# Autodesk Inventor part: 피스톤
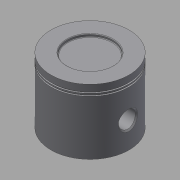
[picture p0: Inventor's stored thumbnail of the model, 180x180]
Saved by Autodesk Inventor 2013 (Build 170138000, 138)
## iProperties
Created: 2016-11
Part Number: 피스톤
Material: 강철, 탄소
Document SubType Name: Modeling
Designer: mduedu
Density: 1 g/cm^3
Author: mduedu
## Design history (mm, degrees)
sketch "스케치1"
  geometry: C1 r 30 at (0, 0); 1 further point
  constraints: 1 centre point, 1 coincident
  dimensions: "d0" = 60 diameter of C1
extrude "돌출1" new body sketch "스케치1" distance "d1" = 50; taper "d2" = 0 deg
sketch "스케치2"
  geometry: C1 r 28 at (0, 0); 1 further point
  constraints: 1 centre point, 1 coincident
  dimensions: "d3" = 56 diameter of C1
extrude "돌출2" cut sketch "스케치2" distance "d4" = 45; taper "d5" = 0 deg
sketch "스케치3"
  geometry: L1 (30, 0)-(30, 50) reference; L2 (30, 45)-(29, 45); L3 (29, 45)-(29, 44); L4 (29, 44)-(30, 44); L5 (30, 44)-(30, 45); L6 (30, 43)-(29, 43); L7 (29, 43)-(29, 42); L8 (29, 42)-(30, 42); L9 (30, 42)-(30, 43); L10 (30, 50)-(-30, 50) reference; L11 (0, 50)-(0, 0)
  constraints: 18 end point, 4 parallel, 3 equal length, 3 perpendicular, 2 horizontal, 2 point on line, 1 midpoint
  dimensions: "d6" = 1 distance of L2.start L2.end; "d8" = 5 distance between parallel lines of L10 L2; "d9" = 1 distance between parallel lines of L6 L4
revolve "회전1" sketch "스케치3" stored, may be unused: angle "d10" = 90 deg
node "작업 평면1"
sketch "스케치4"
  geometry: C1 r 10 at (20, 0); C2 r 6.5 at (20, 0); 1 further point
  constraints: 2 centre point, 1 coincident, 1 horizontal alignment
  dimensions: "d12" = 20 diameter of C1; "d13" = 13 diameter of C2; "d14" = 20 distance of point (0, 0) C1.centre
extrude "돌출3" join sketch "스케치4" stored distance "d15" = 11.75; taper "d16" = 0 deg
extrude "돌출4" cut sketch "스케치4" stored distance "d17" = 72; taper "d18" = 0 deg
fillet "모깎기1" dims "d19" = 3
fillet "모깎기2" dims "d20" = 3
chamfer "모따기1" distance "d21" = 1; stored, may be unused: second distance "d22" = 2, angle "d23" = 45 deg
chamfer "모따기2" distance "d24" = 1; stored, may be unused: second distance "d25" = 2, angle "d26" = 45 deg
sketch "스케치5"
  geometry: C1 r 17.5 at (0, 0); 1 further point
  constraints: 1 centre point, 1 coincident
  dimensions: "d27" = 35 diameter of C1
extrude "돌출5" cut sketch "스케치5" distance "d28" = 2; taper "d29" = 0 deg
fillet "모깎기3" dims "d30" = 0.5
node "솔리드1"
mirror "대칭1"
